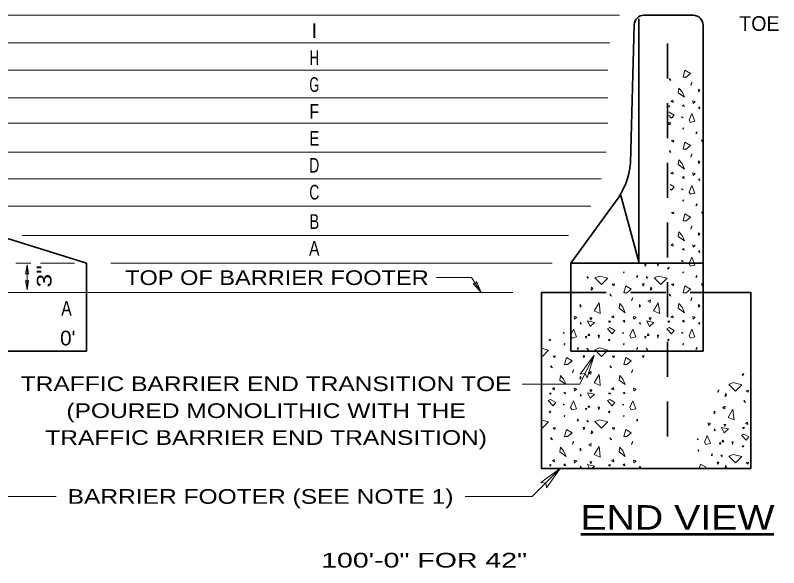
# Model space of a CAD drawing. Extents: x -15.1 to -7.9, y 13.6 to 23.8.
# Drawn here: x -11.564 to -8.443, y 19.638 to 21.898 of the extents above; entities that cross this region are included whole.
import ezdxf
from ezdxf.enums import TextEntityAlignment as Align

# ---------------------------------------------------------------- set-up
doc = ezdxf.new("R2010")
doc.units = 0
doc.header["$LTSCALE"] = 0.024
doc.header["$PDMODE"] = 32
doc.header["$PDSIZE"] = 0.012
doc.linetypes.add('LONG_DASHED', pattern=[7.5, 6, -1.5])
for name, color, linetype, lineweight in [('1', 7, 'Continuous', 35), ('10', 7, 'Continuous', 13), ('12', 7, 'Continuous', 53), ('6', 7, 'Continuous', 13)]:
    doc.layers.add(name, color=color, linetype=linetype, lineweight=lineweight)

msp = doc.modelspace()

# ---------------------------------------------------------------- linework, layer by layer
at = {"layer": '1'}
for p, q in [((-14.51633, 21.89767), (-11.27283, 20.88417)), ((-8.99367, 21.89767), (-8.7925, 21.89767)), ((-9.03367, 21.859), (-9.04883, 21.29367)), ((-8.7525, 20.88417), (-8.7525, 21.85767)), ((-9.29267, 20.88417), (-9.11133, 21.13367))]:
    msp.add_line(p, q, dxfattribs=at)
at = {"layer": '1', "linetype": 'LONG_DASHED'}
for p, q in [((-8.897, 21.78267), (-8.897, 20.121)), ((-9.29267, 20.76417), (-8.7525, 20.76417))]:
    msp.add_line(p, q, dxfattribs=at)
at = {"layer": '1'}
for points in [[(-9.0155, 21.88367), (-9.0155, 20.88867), (-9.08867, 21.16067)], [(-11.993, 20.524), (-11.27283, 20.524), (-11.27283, 20.88417)], [(-9.29267, 20.76417), (-9.29267, 20.88417), (-8.7525, 20.88417), (-8.7525, 20.76417)], [(-8.55667, 20.044), (-9.41267, 20.044), (-9.41267, 20.76417), (-9.29267, 20.76417), (-9.29267, 20.524), (-8.7525, 20.524), (-8.7525, 20.76417)], [(-8.55667, 20.044), (-8.55667, 20.76417), (-8.7525, 20.76417)]]:
    msp.add_lwpolyline(points, dxfattribs=at)
for centre, radius, start, end in [((-8.99373, 21.85767), 0.04001, 90, 177.99907), ((-8.79251, 21.85767), 0.04001, 0, 90), ((-9.35344, 21.32023), 0.30568, 322.39076, 355.02255)]:
    msp.add_arc(centre, radius, start, end, dxfattribs=at)
at = {"layer": '10'}
for p, q in [((-14.41633, 21.89767), (-9.09375, 21.89767)), ((-14.05633, 21.78433), (-9.13367, 21.78433)), ((-13.69633, 21.67267), (-9.14125, 21.67267)), ((-13.33633, 21.56017), (-9.14125, 21.56017)), ((-12.97617, 21.45617), (-9.14125, 21.45617)), ((-12.61617, 21.33767), (-9.14883, 21.33767)), ((-12.25617, 21.22917), (-9.16858, 21.22917)), ((-11.896, 21.11717), (-9.21133, 21.11717)), ((-11.536, 20.99767), (-9.302, 20.99767)), ((-11.56217, 20.88417), (-11.5005, 20.88417)), ((-11.4605, 20.88417), (-11.32133, 20.88417)), ((-9.39267, 20.88417), (-11.17283, 20.88417)), ((-9.41883, 20.88417), (-9.36967, 20.88417)), ((-11.52233, 20.83833), (-11.516, 20.87683)), ((-11.516, 20.775), (-11.516, 20.87683)), ((-11.5095, 20.83833), (-11.516, 20.87683)), ((-11.52233, 20.83833), (-11.516, 20.84317)), ((-11.5095, 20.83833), (-11.516, 20.84317)), ((-9.84233, 20.82467), (-9.6995, 20.82467)), ((-9.6995, 20.82467), (-9.65933, 20.7645)), ((-11.52233, 20.8135), (-11.516, 20.775)), ((-11.52233, 20.8135), (-11.516, 20.80867)), ((-11.5095, 20.8135), (-11.516, 20.775)), ((-11.5095, 20.8135), (-11.516, 20.80867)), ((-9.69183, 20.80083), (-9.65933, 20.7645)), ((-9.69183, 20.80083), (-9.68183, 20.8)), ((-9.67833, 20.80933), (-9.68183, 20.8)), ((-9.67833, 20.80933), (-9.65933, 20.7645)), ((-9.52933, 20.7645), (-11.71933, 20.7645)), ((-9.2565, 20.38933), (-9.19733, 20.508)), ((-9.2545, 20.42933), (-9.19733, 20.508)), ((-9.22583, 20.415), (-9.19733, 20.508)), ((-9.2545, 20.42933), (-9.23483, 20.43283)), ((-9.22583, 20.415), (-9.23483, 20.43283)), ((-9.49117, 20.38933), (-9.2565, 20.38933)), ((-9.45033, 19.92983), (-9.33617, 20.044)), ((-9.41533, 19.98733), (-9.33617, 20.044)), ((-9.39267, 19.96483), (-9.33617, 20.044)), ((-9.41533, 19.98733), (-9.3955, 19.9845)), ((-9.39267, 19.96483), (-9.3955, 19.9845)), ((-11.681, 19.92983), (-11.39683, 19.92983)), ((-9.72483, 19.92983), (-9.45033, 19.92983))]:
    msp.add_line(p, q, dxfattribs=at)
at = {"layer": '12'}
msp.add_line((-9.2515, 19.77567), (-8.46267, 19.77567), dxfattribs=at)
at = {"layer": '6'}
for points in [[(-8.82183, 21.644), (-8.8035, 21.6595), (-8.82617, 21.67283), (-8.83367, 21.644)], [(-8.88983, 21.63967), (-8.88983, 21.635), (-8.88367, 21.63067)], [(-8.85067, 21.6), (-8.8535, 21.58067), (-8.82783, 21.56233), (-8.83833, 21.585)], [(-8.802, 21.61233), (-8.8005, 21.61233), (-8.79767, 21.6245)], [(-8.77033, 21.59583), (-8.77033, 21.585), (-8.76567, 21.591)], [(-8.87617, 21.55033), (-8.88367, 21.54433), (-8.87467, 21.541)], [(-8.7945, 21.54717), (-8.793, 21.53667), (-8.784, 21.54433)], [(-8.83683, 21.52767), (-8.82933, 21.5245), (-8.83083, 21.532)], [(-8.77033, 21.51833), (-8.76567, 21.5155), (-8.767, 21.523)], [(-8.8355, 21.4805), (-8.83983, 21.482), (-8.8355, 21.47767)], [(-8.8035, 21.45933), (-8.7855, 21.464), (-8.79767, 21.49567), (-8.8095, 21.46867)], [(-8.83217, 21.43667), (-8.8355, 21.43367), (-8.83367, 21.4305)], [(-8.77783, 21.4215), (-8.78217, 21.414), (-8.77783, 21.414)], [(-8.88083, 21.38517), (-8.87333, 21.379), (-8.87183, 21.3865)], [(-8.82183, 21.35017), (-8.8035, 21.36567), (-8.82617, 21.379), (-8.83367, 21.35017)], [(-8.802, 21.3185), (-8.8005, 21.3185), (-8.79767, 21.33083)], [(-8.85067, 21.30633), (-8.8535, 21.28683), (-8.82783, 21.2685), (-8.83833, 21.29117)], [(-8.77033, 21.302), (-8.77033, 21.29117), (-8.76567, 21.29733)], [(-8.87617, 21.2565), (-8.88367, 21.2505), (-8.87467, 21.24717)], [(-8.83683, 21.23383), (-8.82933, 21.23067), (-8.83083, 21.23817)], [(-8.7945, 21.25333), (-8.793, 21.24283), (-8.784, 21.2505)], [(-8.77033, 21.2245), (-8.76567, 21.22167), (-8.767, 21.22917)], [(-8.8035, 21.1655), (-8.7855, 21.17017), (-8.79767, 21.20183), (-8.8095, 21.17483)], [(-8.8355, 21.18667), (-8.83983, 21.18817), (-8.8355, 21.18383)], [(-8.83217, 21.14283), (-8.8355, 21.14), (-8.83367, 21.13667)], [(-8.77783, 21.12767), (-8.78217, 21.12017), (-8.77783, 21.12017)], [(-8.88083, 21.09133), (-8.87333, 21.08517), (-8.87183, 21.09283)], [(-8.82183, 21.05633), (-8.8035, 21.07183), (-8.82617, 21.08517), (-8.83367, 21.05633)], [(-8.802, 21.02467), (-8.8005, 21.02467), (-8.79767, 21.037)], [(-8.85067, 21.0125), (-8.8535, 20.993), (-8.82783, 20.97467), (-8.83833, 20.99733)], [(-8.77033, 21.00817), (-8.77033, 20.99733), (-8.76567, 21.0035)], [(-8.83683, 20.94017), (-8.82933, 20.93683), (-8.83083, 20.94433)], [(-8.7945, 20.9595), (-8.793, 20.94917), (-8.784, 20.95667)], [(-8.77033, 20.93067), (-8.76567, 20.92783), (-8.767, 20.93533)], [(-8.8355, 20.893), (-8.83983, 20.89433), (-8.8355, 20.89)], [(-8.8035, 20.87167), (-8.7855, 20.87633), (-8.79767, 20.908), (-8.8095, 20.881)], [(-9.0745, 20.849), (-9.07783, 20.84617), (-9.076, 20.84283)], [(-8.99, 20.87783), (-8.9885, 20.87167), (-8.98533, 20.87783)], [(-8.89733, 20.86267), (-8.89317, 20.85983), (-8.89133, 20.86733)], [(-8.83217, 20.849), (-8.8355, 20.84617), (-8.83367, 20.84283)], [(-9.22283, 20.822), (-9.22, 20.8235), (-9.2275, 20.8295)], [(-9.17617, 20.831), (-9.14117, 20.822), (-9.16717, 20.796), (-9.1945, 20.8235)], [(-9.02017, 20.83383), (-9.0245, 20.82633), (-9.02017, 20.82633)], [(-8.9805, 20.822), (-8.97767, 20.8235), (-8.98533, 20.8295)], [(-8.93383, 20.831), (-8.89883, 20.822), (-8.92483, 20.796), (-8.95217, 20.8235)], [(-8.77783, 20.83383), (-8.78217, 20.82633), (-8.77783, 20.82633)], [(-9.12317, 20.7975), (-9.11567, 20.79133), (-9.11417, 20.799)], [(-9.06417, 20.7625), (-9.04567, 20.778), (-9.0685, 20.79133), (-9.076, 20.7625)], [(-9.00033, 20.799), (-8.9975, 20.79), (-8.99283, 20.799)], [(-8.88083, 20.7975), (-8.87333, 20.79133), (-8.87183, 20.799)], [(-8.82183, 20.7625), (-8.8035, 20.778), (-8.82617, 20.79133), (-8.83367, 20.7625)], [(-9.20783, 20.78567), (-9.2095, 20.77333), (-9.2035, 20.7795)], [(-9.13217, 20.75833), (-9.13217, 20.7535), (-9.126, 20.74933)], [(-8.9655, 20.78567), (-8.96733, 20.77333), (-8.96117, 20.7795)], [(-8.88983, 20.75833), (-8.88983, 20.7535), (-8.88367, 20.74933)], [(-9.04433, 20.73083), (-9.04283, 20.73083), (-9.04, 20.74317)], [(-8.97767, 20.728), (-8.96867, 20.72333), (-8.96733, 20.73417)], [(-8.802, 20.73083), (-8.8005, 20.73083), (-8.79767, 20.74317)], [(-9.255, 20.71433), (-9.255, 20.7035), (-9.25033, 20.70967)], [(-9.17467, 20.696), (-9.17317, 20.678), (-9.19733, 20.68833), (-9.1775, 20.72183)], [(-9.09283, 20.71867), (-9.09583, 20.69917), (-9.07017, 20.68083), (-9.08067, 20.7035)], [(-9.01267, 20.71433), (-9.01267, 20.7035), (-9.008, 20.70967)], [(-8.93233, 20.696), (-8.93083, 20.678), (-8.955, 20.68833), (-8.93517, 20.72183)], [(-8.85067, 20.71867), (-8.8535, 20.69917), (-8.82783, 20.68083), (-8.83833, 20.7035)], [(-8.77033, 20.71433), (-8.77033, 20.7035), (-8.76567, 20.70967)], [(-9.279, 20.66567), (-9.27767, 20.65533), (-9.26867, 20.66283)], [(-9.1185, 20.669), (-9.126, 20.66283), (-9.117, 20.65967)], [(-9.03667, 20.66567), (-9.03533, 20.65533), (-9.02633, 20.66283)], [(-8.87617, 20.669), (-8.88367, 20.66283), (-8.87467, 20.65967)], [(-8.7945, 20.66567), (-8.793, 20.65533), (-8.784, 20.66283)], [(-9.255, 20.637), (-9.25033, 20.634), (-9.25167, 20.64167)], [(-9.22467, 20.64767), (-9.21383, 20.625), (-9.19583, 20.64167)], [(-9.21533, 20.65967), (-9.211, 20.65067), (-9.20633, 20.65967)], [(-9.13833, 20.64633), (-9.13367, 20.64167), (-9.13067, 20.64633)], [(-9.07917, 20.64633), (-9.07167, 20.643), (-9.07317, 20.65067)], [(-9.01267, 20.637), (-9.008, 20.634), (-9.00933, 20.64167)], [(-8.98233, 20.64767), (-8.9715, 20.625), (-8.9535, 20.64167)], [(-8.973, 20.65967), (-8.96867, 20.65067), (-8.964, 20.65967)], [(-8.896, 20.64633), (-8.89133, 20.64167), (-8.88833, 20.64633)], [(-8.83683, 20.64633), (-8.82933, 20.643), (-8.83083, 20.65067)], [(-8.77033, 20.637), (-8.76567, 20.634), (-8.767, 20.64167)], [(-9.32017, 20.59917), (-9.3245, 20.6005), (-9.32017, 20.59617)], [(-9.288, 20.57783), (-9.27, 20.5825), (-9.28233, 20.61417), (-9.29417, 20.58717)], [(-9.143, 20.616), (-9.12317, 20.59483), (-9.11233, 20.60817), (-9.13367, 20.62033)], [(-9.07783, 20.59917), (-9.08217, 20.6005), (-9.07783, 20.59617)], [(-9.04567, 20.57783), (-9.02767, 20.5825), (-9.04, 20.61417), (-9.05183, 20.58717)], [(-8.90067, 20.616), (-8.88083, 20.59483), (-8.87, 20.60817), (-8.89133, 20.62033)], [(-8.8355, 20.59917), (-8.83983, 20.6005), (-8.8355, 20.59617)], [(-8.8035, 20.57783), (-8.7855, 20.5825), (-8.79767, 20.61417), (-8.8095, 20.58717)], [(-9.382, 20.56883), (-9.37767, 20.566), (-9.376, 20.5735)], [(-9.23233, 20.584), (-9.23083, 20.57783), (-9.2275, 20.584)], [(-9.2185, 20.59483), (-9.21533, 20.58867), (-9.22283, 20.58867)], [(-9.18083, 20.59017), (-9.179, 20.57783), (-9.17617, 20.58867)], [(-9.13967, 20.56883), (-9.13533, 20.566), (-9.13367, 20.5735)], [(-8.99, 20.584), (-8.9885, 20.57783), (-8.98533, 20.584)], [(-8.97633, 20.59483), (-8.973, 20.58867), (-8.9805, 20.58867)], [(-8.9385, 20.59017), (-8.93667, 20.57783), (-8.93383, 20.58867)], [(-8.89733, 20.56883), (-8.89317, 20.566), (-8.89133, 20.5735)], [(-9.31683, 20.55517), (-9.32017, 20.55233), (-9.31833, 20.549)], [(-9.2625, 20.54), (-9.26683, 20.5325), (-9.2625, 20.5325)], [(-9.17617, 20.53717), (-9.14117, 20.52817), (-9.16717, 20.50233), (-9.1945, 20.52967)], [(-9.0745, 20.55517), (-9.07783, 20.55233), (-9.076, 20.549)], [(-9.02017, 20.54), (-9.0245, 20.5325), (-9.02017, 20.5325)], [(-8.83217, 20.55517), (-8.8355, 20.55233), (-8.83367, 20.549)], [(-8.77783, 20.54), (-8.78217, 20.5325), (-8.77783, 20.5325)], [(-9.22283, 20.52817), (-9.22, 20.52967), (-9.2275, 20.53567)], [(-8.9805, 20.52817), (-8.97767, 20.52967), (-8.98533, 20.53567)], [(-9.3655, 20.50367), (-9.358, 20.4975), (-9.3565, 20.50517)], [(-9.3065, 20.46883), (-9.288, 20.48433), (-9.31083, 20.4975), (-9.31833, 20.46883)], [(-9.24267, 20.50517), (-9.23983, 20.49617), (-9.23517, 20.50517)], [(-9.20783, 20.49183), (-9.2095, 20.4795), (-9.2035, 20.48567)], [(-9.12317, 20.50367), (-9.11567, 20.4975), (-9.11417, 20.50517)], [(-9.06417, 20.46883), (-9.04567, 20.48433), (-9.0685, 20.4975), (-9.076, 20.46883)], [(-9.00033, 20.50517), (-8.9975, 20.49617), (-8.99283, 20.50517)], [(-9.3745, 20.4645), (-9.3745, 20.45983), (-9.36833, 20.4555)], [(-9.28667, 20.43717), (-9.28517, 20.43717), (-9.28233, 20.44933)], [(-9.13217, 20.4645), (-9.13217, 20.45983), (-9.126, 20.4555)], [(-9.04433, 20.43717), (-9.04283, 20.43717), (-9.04, 20.44933)], [(-9.33517, 20.42483), (-9.33817, 20.40533), (-9.3125, 20.387), (-9.323, 20.40967)], [(-9.255, 20.4205), (-9.255, 20.40967), (-9.25033, 20.41583)], [(-9.22, 20.43417), (-9.211, 20.4295), (-9.2095, 20.44033)], [(-9.17467, 20.40217), (-9.17317, 20.38417), (-9.19733, 20.39467), (-9.1775, 20.42817)], [(-9.09283, 20.42483), (-9.09583, 20.40533), (-9.07017, 20.387), (-9.08067, 20.40967)], [(-8.59217, 20.4275), (-8.58783, 20.42467), (-8.586, 20.43217)], [(-8.6285, 20.39583), (-8.59367, 20.38683), (-8.6195, 20.36083), (-8.647, 20.38817)], [(-9.38067, 20.3525), (-9.376, 20.34783), (-9.373, 20.3525)], [(-9.36083, 20.37517), (-9.36833, 20.369), (-9.35933, 20.36583)], [(-9.3215, 20.3525), (-9.314, 20.34917), (-9.3155, 20.35683)], [(-9.279, 20.372), (-9.27767, 20.3615), (-9.26867, 20.369)], [(-9.22467, 20.35383), (-9.21383, 20.33117), (-9.19583, 20.34783)], [(-9.21533, 20.36583), (-9.211, 20.35683), (-9.20633, 20.36583)], [(-9.13833, 20.3525), (-9.13367, 20.34783), (-9.13067, 20.3525)], [(-9.1185, 20.37517), (-9.126, 20.369), (-9.117, 20.36583)], [(-9.07917, 20.3525), (-9.07167, 20.34917), (-9.07317, 20.35683)], [(-9.03667, 20.372), (-9.03533, 20.3615), (-9.02633, 20.369)], [(-8.66017, 20.3505), (-8.662, 20.33817), (-8.656, 20.34433)], [(-8.57567, 20.36233), (-8.568, 20.35617), (-8.56667, 20.36383)], [(-9.38533, 20.32217), (-9.3655, 20.301), (-9.35467, 20.31433), (-9.376, 20.3265)], [(-9.288, 20.284), (-9.27, 20.28867), (-9.28233, 20.3205), (-9.29417, 20.2935)], [(-9.255, 20.34317), (-9.25033, 20.34017), (-9.25167, 20.34783)], [(-9.143, 20.32217), (-9.12317, 20.301), (-9.11233, 20.31433), (-9.13367, 20.3265)], [(-9.04567, 20.284), (-9.02767, 20.28867), (-9.04, 20.3205), (-9.05183, 20.2935)], [(-8.58467, 20.323), (-8.58467, 20.31833), (-8.5785, 20.314)], [(-9.32017, 20.30533), (-9.3245, 20.30667), (-9.32017, 20.3025)], [(-9.23233, 20.29017), (-9.23083, 20.284), (-9.2275, 20.29017)], [(-9.2185, 20.301), (-9.21533, 20.29483), (-9.22283, 20.29483)], [(-9.18083, 20.29633), (-9.179, 20.284), (-9.17617, 20.29483)], [(-9.07783, 20.30533), (-9.08217, 20.30667), (-9.07783, 20.3025)], [(-8.6725, 20.29283), (-8.6635, 20.28817), (-8.662, 20.299)], [(-9.382, 20.275), (-9.37767, 20.27217), (-9.376, 20.27967)], [(-9.31683, 20.26133), (-9.32017, 20.2585), (-9.31833, 20.25533)], [(-9.13967, 20.275), (-9.13533, 20.27217), (-9.13367, 20.27967)], [(-9.0745, 20.26133), (-9.07783, 20.2585), (-9.076, 20.25533)], [(-8.70733, 20.27917), (-8.70733, 20.26833), (-8.70267, 20.2745)], [(-8.62717, 20.26083), (-8.62567, 20.24283), (-8.64983, 20.25317), (-8.63, 20.28667)], [(-9.2625, 20.24633), (-9.26683, 20.23867), (-9.2625, 20.23867)], [(-9.22283, 20.23433), (-9.22, 20.23583), (-9.2275, 20.242)], [(-9.17617, 20.24333), (-9.14117, 20.23433), (-9.16717, 20.2085), (-9.1945, 20.23583)], [(-9.02017, 20.24633), (-9.0245, 20.23867), (-9.02017, 20.23867)], [(-8.7315, 20.2305), (-8.73017, 20.22017), (-8.72117, 20.22767)], [(-8.571, 20.23383), (-8.5785, 20.22767), (-8.5695, 20.22433)], [(-9.3655, 20.20983), (-9.358, 20.20383), (-9.3565, 20.21133)], [(-9.3065, 20.175), (-9.288, 20.1905), (-9.31083, 20.20383), (-9.31833, 20.175)], [(-9.24267, 20.21133), (-9.23983, 20.20233), (-9.23517, 20.21133)], [(-9.20783, 20.198), (-9.2095, 20.18583), (-9.2035, 20.19183)], [(-9.12317, 20.20983), (-9.11567, 20.20383), (-9.11417, 20.21133)], [(-9.06417, 20.175), (-9.04567, 20.1905), (-9.0685, 20.20383), (-9.076, 20.175)], [(-8.70733, 20.20167), (-8.70267, 20.19883), (-8.70417, 20.20633)], [(-8.67717, 20.2125), (-8.66633, 20.18983), (-8.64833, 20.20633)], [(-8.66783, 20.22433), (-8.6635, 20.21533), (-8.65883, 20.22433)], [(-8.59083, 20.21117), (-8.586, 20.20633), (-8.58317, 20.21117)], [(-9.3745, 20.17067), (-9.3745, 20.166), (-9.36833, 20.16167)], [(-9.13217, 20.17067), (-9.13217, 20.166), (-9.126, 20.16167)], [(-8.77267, 20.164), (-8.77683, 20.16533), (-8.77267, 20.161)], [(-8.7405, 20.14267), (-8.7225, 20.14733), (-8.73483, 20.179), (-8.74667, 20.152)], [(-8.5955, 20.18083), (-8.57567, 20.15967), (-8.56483, 20.173), (-8.586, 20.18517)], [(-9.28667, 20.14333), (-9.28517, 20.14333), (-9.28233, 20.1555)], [(-9.22, 20.14033), (-9.211, 20.13567), (-9.2095, 20.1465)], [(-9.17467, 20.10833), (-9.17317, 20.09033), (-9.19733, 20.10083), (-9.1775, 20.13433)], [(-9.04433, 20.14333), (-9.04283, 20.14333), (-9.04, 20.1555)], [(-8.68467, 20.14883), (-8.68333, 20.14267), (-8.68, 20.14883)], [(-8.671, 20.15967), (-8.66783, 20.1535), (-8.67533, 20.1535)], [(-8.63317, 20.155), (-8.6315, 20.14267), (-8.6285, 20.1535)], [(-8.59217, 20.13367), (-8.58783, 20.13083), (-8.586, 20.13833)], [(-9.33517, 20.131), (-9.33817, 20.11167), (-9.3125, 20.09317), (-9.323, 20.11583)], [(-9.255, 20.12667), (-9.255, 20.11583), (-9.25033, 20.122)], [(-9.09283, 20.131), (-9.09583, 20.11167), (-9.07017, 20.09317), (-9.08067, 20.11583)], [(-8.76933, 20.12), (-8.77267, 20.11717), (-8.77083, 20.11383)], [(-8.715, 20.10483), (-8.71933, 20.09733), (-8.715, 20.09733)], [(-8.67533, 20.093), (-8.6725, 20.0945), (-8.68, 20.1005)], [(-8.6285, 20.102), (-8.59367, 20.093), (-8.6195, 20.067), (-8.647, 20.0945)], [(-9.36083, 20.08133), (-9.36833, 20.07517), (-9.35933, 20.072)], [(-9.279, 20.07817), (-9.27767, 20.06767), (-9.26867, 20.07517)], [(-9.21533, 20.072), (-9.211, 20.063), (-9.20633, 20.072)], [(-9.1185, 20.08133), (-9.126, 20.07517), (-9.117, 20.072)], [(-9.03667, 20.07817), (-9.03533, 20.06767), (-9.02633, 20.07517)], [(-8.69517, 20.07), (-8.69233, 20.061), (-8.68767, 20.07)], [(-8.57567, 20.0685), (-8.568, 20.06233), (-8.56667, 20.07)], [(-9.38067, 20.05867), (-9.376, 20.054), (-9.373, 20.05867)], [(-9.3215, 20.05867), (-9.314, 20.0555), (-9.3155, 20.063)], [(-9.255, 20.04933), (-9.25033, 20.0465), (-9.25167, 20.054)], [(-9.13833, 20.05867), (-9.13367, 20.054), (-9.13067, 20.05867)], [(-9.07917, 20.05867), (-9.07167, 20.0555), (-9.07317, 20.063)], [(-9.01267, 20.04933), (-9.008, 20.0465), (-9.00933, 20.054)], [(-8.66017, 20.05667), (-8.662, 20.04433), (-8.656, 20.0505)]]:
    msp.add_lwpolyline(points, close=True, dxfattribs=at)
for points in [[(-8.8925, 21.52433), (-8.89133, 21.523), (-8.88833, 21.52767), (-8.89267, 21.52767)], [(-8.89183, 21.488), (-8.88083, 21.47617), (-8.87, 21.4895), (-8.89133, 21.50183), (-8.89217, 21.50133)], [(-8.7525, 21.3865), (-8.758, 21.3865), (-8.75517, 21.3775), (-8.7525, 21.38267)], [(-8.88917, 21.34083), (-8.88367, 21.33683), (-8.88933, 21.345)], [(-8.8865, 21.1885), (-8.88083, 21.18233), (-8.87, 21.19567), (-8.88683, 21.20533)], [(-8.7525, 21.09283), (-8.758, 21.09283), (-8.75517, 21.08383), (-8.7525, 21.08883)], [(-8.88383, 21.04317), (-8.88367, 21.043), (-8.88383, 21.04333)], [(-8.88233, 20.95617), (-8.87467, 20.95333), (-8.87617, 20.96283), (-8.88233, 20.95783)], [(-9.21583, 20.88333), (-9.21533, 20.8825), (-9.22283, 20.8825), (-9.22217, 20.8835)], [(-8.938, 20.88083), (-8.93667, 20.87167), (-8.93417, 20.88083)], [(-8.7525, 20.799), (-8.758, 20.799), (-8.75517, 20.79), (-8.7525, 20.79517)], [(-9.40867, 20.53467), (-9.3835, 20.52817), (-9.409, 20.50267)], [(-8.69383, 20.35933), (-8.69233, 20.35483), (-8.68767, 20.36383), (-8.69033, 20.36383)], [(-9.411, 20.2415), (-9.3835, 20.23433), (-9.40933, 20.2085), (-9.41133, 20.21033)], [(-9.20683, 20.044), (-9.19583, 20.054), (-9.22467, 20.06017), (-9.217, 20.044)], [(-8.7465, 20.044), (-8.7405, 20.049), (-8.76317, 20.06233), (-8.768, 20.044)]]:
    msp.add_lwpolyline(points, dxfattribs=at)
msp.add_point((-8.89133, 21.455), dxfattribs=at)

# ---------------------------------------------------------------- texts
at = {"layer": '12'}
msp.add_text('TOE', height=0.06001, dxfattribs=at).set_placement((-8.60442, 21.83392))
msp.add_text('I', height=0.06001, dxfattribs=at).set_placement((-10.34158, 21.80425), align=Align.CENTER)
for s, height, width, p in [('H', 0.06001, 0.65, (-10.34158, 21.69417)), ('G', 0.06001, 0.65, (-10.34158, 21.58417)), ('F', 0.06001, 0.8, (-10.34158, 21.47417)), ('E', 0.06001, 0.75, (-10.34158, 21.36417)), ('D', 0.06001, 0.7, (-10.34158, 21.25417)), ('C', 0.06001, 0.7, (-10.34158, 21.14408)), ('B', 0.06001, 0.75, (-10.34158, 21.02408)), ('A', 0.06001, 0.8, (-10.34163, 20.91408)), ('TRAFFIC BARRIER END TRANSITION TOE', 0.06001, 1.25, (-10.53854, 20.36067)), ('(POURED MONOLITHIC WITH THE', 0.06001, 1.25, (-10.53854, 20.25067)), ('TRAFFIC BARRIER END TRANSITION)', 0.06001, 1.25, (-10.53854, 20.14067)), ('BARRIER FOOTER (SEE NOTE 1)', 0.06001, 1.25, (-10.56129, 19.89975)), ('END VIEW', 0.1, 1.2, (-8.85704, 19.79425)), ('100\'-0" FOR 42"', 0.06, 1.45, (-9.89242, 19.63917))]:
    msp.add_text(s, height=height, dxfattribs=dict(at, width=width)).set_placement(p, align=Align.CENTER)
at = {"layer": '12', "width": 1.25}
msp.add_text('3"', height=0.06001, rotation=90, dxfattribs=at).set_placement((-11.41592, 20.83004), align=Align.CENTER)
at = {"layer": '12', "width": 1.2}
msp.add_text('TOP OF BARRIER FOOTER', height=0.06001, dxfattribs=at).set_placement((-9.87383, 20.79458), align=Align.RIGHT)
at = {"layer": '12'}
for s, width, p in [('A', 0.8, (-11.37608, 20.66925)), ("0'", 1.05, (-11.38075, 20.54767))]:
    msp.add_text(s, height=0.06001, dxfattribs=dict(at, width=width)).set_placement(p)

doc.saveas('drawing.dxf')
